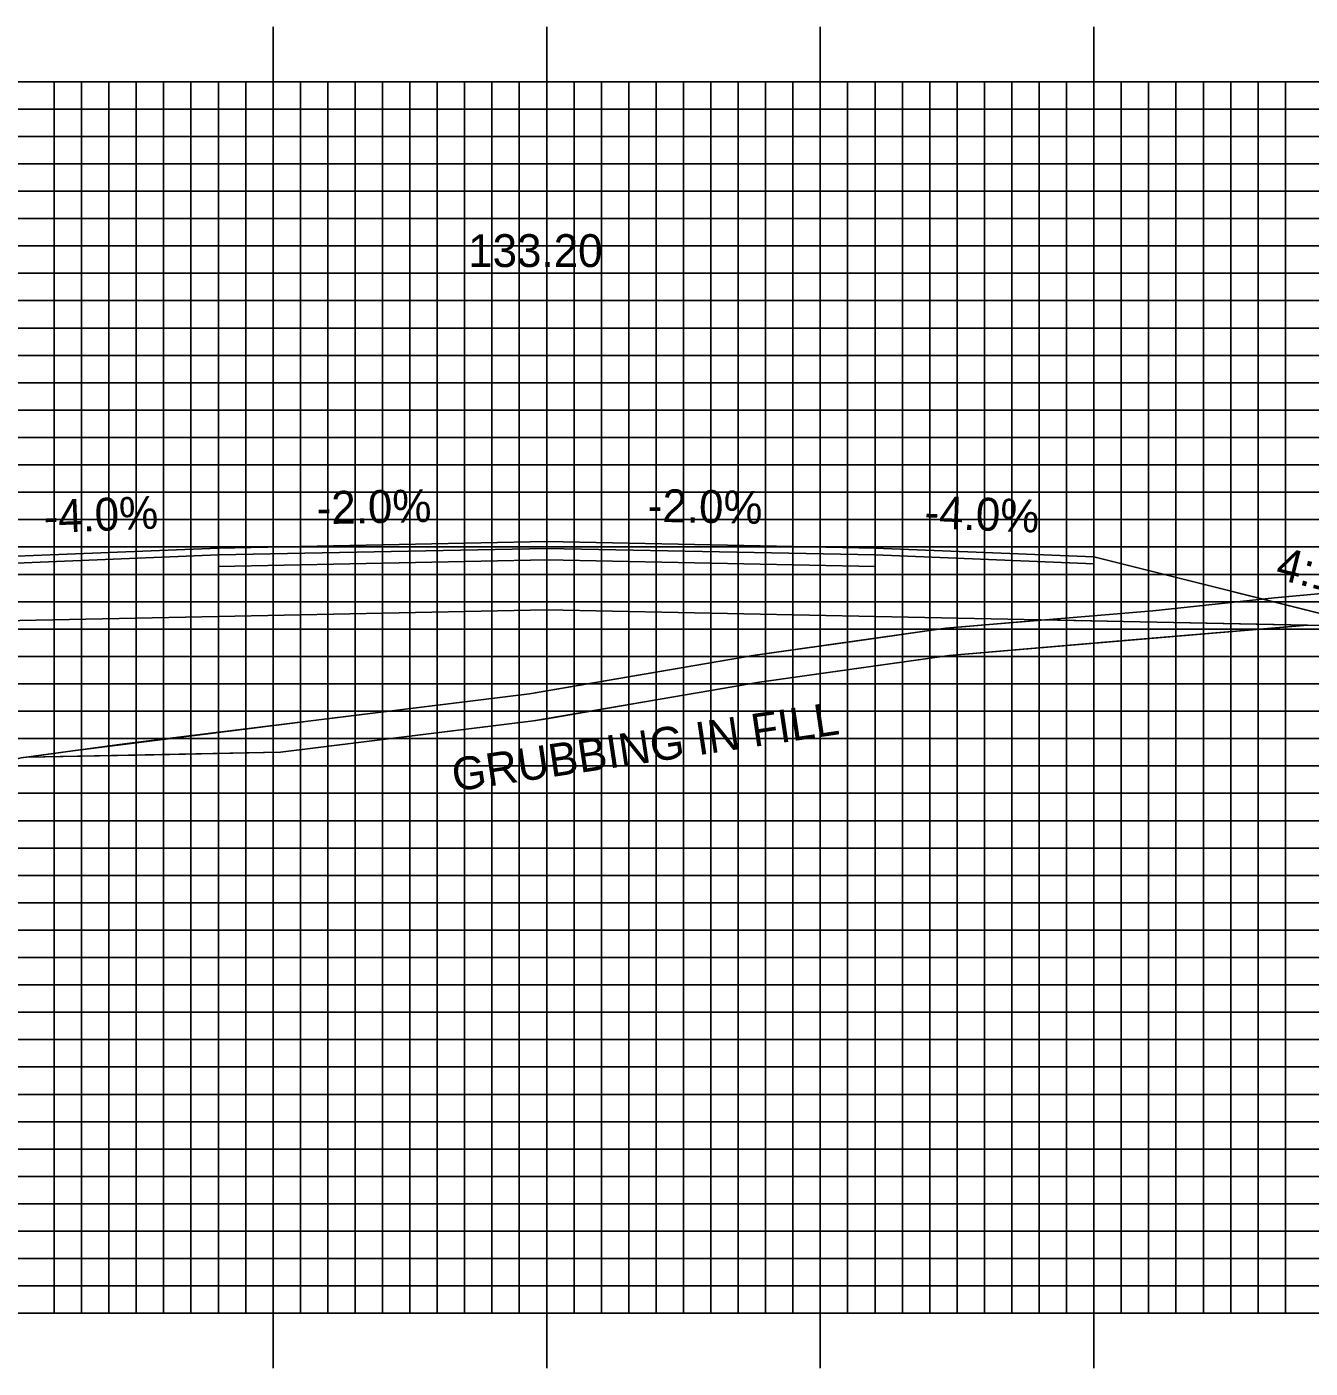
# Model space of a CAD drawing. Extents: x 1782254 to 1782597, y 442591 to 442811.
# Drawn here: x 1782400.43 to 1782447.34, y 442716.66 to 442765.67 of the extents above; entities that cross this region are included whole.
import ezdxf

# ---------------------------------------------------------------- set-up
doc = ezdxf.new("R2010")
doc.units = 0
for name, color, linetype in [('ANNOTATION', 7, 'Continuous'), ('D_Roadway_Centerline', 7, 'Continuous'), ('D_Roadway_Centerline_Text', 7, 'Continuous'), ('D_Roadway_Edge_Shoulder', 7, 'Continuous'), ('D_Roadway_Edge_TW', 7, 'Continuous'), ('D_Roadway_Pavement', 7, 'Continuous'), ('D_Roadway_SlopeLines', 7, 'Continuous'), ('D_Roadway_SubGrade', 7, 'Continuous'), ('GRUBBING IN FILL', 7, 'Continuous'), ('MAJOR', 7, 'Continuous'), ('MINOR', 7, 'Continuous'), ('S_Roadway_Centerline', 7, 'Continuous')]:
    doc.layers.add(name, color=color, linetype=linetype)

msp = doc.modelspace()

# ---------------------------------------------------------------- linework, layer by layer
at = {"layer": 'D_Roadway_Centerline'}
msp.add_lwpolyline([(1782351.984, 442731.486), (1782387.434, 442743.303), (1782389.26, 442743.759), (1782399.434, 442746.303), (1782407.434, 442746.623), (1782419.434, 442746.863), (1782431.434, 442746.623), (1782439.434, 442746.303), (1782449.608, 442743.759), (1782453.608, 442742.759), (1782457.483, 442744.696), (1782458.733, 442745.255), (1782459.983, 442745.682), (1782461.233, 442745.977), (1782462.483, 442746.14)], dxfattribs=at)
at = {"layer": 'D_Roadway_Edge_Shoulder'}
for points in [[(1782407.434, 442746.623), (1782399.434, 442746.303), (1782399.434, 442746.053), (1782407.434, 442746.373)], [(1782431.434, 442746.623), (1782439.434, 442746.303), (1782439.434, 442746.053), (1782431.434, 442746.373)]]:
    msp.add_lwpolyline(points, close=True, dxfattribs=at)
at = {"layer": 'D_Roadway_Edge_TW'}
msp.add_lwpolyline([(1782407.434, 442746.373), (1782407.434, 442746.623), (1782419.434, 442746.863), (1782431.434, 442746.623), (1782431.434, 442746.373), (1782419.434, 442746.613)], close=True, dxfattribs=at)
at = {"layer": 'D_Roadway_Pavement'}
msp.add_lwpolyline([(1782407.434, 442745.956), (1782407.434, 442746.373), (1782419.434, 442746.613), (1782431.434, 442746.373), (1782431.434, 442745.956), (1782419.434, 442746.196)], close=True, dxfattribs=at)
at = {"layer": 'D_Roadway_SlopeLines'}
msp.add_lwpolyline([(1782439.434, 442746.303), (1782453.608, 442742.759)], dxfattribs=at)
at = {"layer": 'D_Roadway_SubGrade'}
msp.add_lwpolyline([(1782407.434, 442744.123), (1782389.26, 442743.759), (1782399.434, 442746.303), (1782399.434, 442746.053), (1782407.434, 442746.373), (1782419.434, 442746.613), (1782431.434, 442746.373), (1782439.434, 442746.053), (1782439.434, 442746.303), (1782449.608, 442743.759), (1782431.434, 442744.123), (1782419.434, 442744.363)], close=True, dxfattribs=at)
at = {"layer": 'GRUBBING IN FILL'}
msp.add_line((1782400.434, 442738.983), (1782409.709, 442739.168), dxfattribs=at)
msp.add_line((1782400.434, 442738.983), (1782409.709, 442739.168), dxfattribs=at)
msp.add_lwpolyline([(1782409.709, 442739.168), (1782418.947, 442740.308), (1782427.208, 442741.722), (1782434.14, 442742.702), (1782447.244, 442743.806)], dxfattribs=at)
msp.add_lwpolyline([(1782409.709, 442739.168), (1782418.947, 442740.308), (1782427.208, 442741.722), (1782434.14, 442742.702), (1782447.244, 442743.806)], dxfattribs=at)
for points in [[(1782419.434, 442741.406), (1782422.928, 442742.004), (1782427.054, 442742.71), (1782430.541, 442743.203), (1782434.028, 442743.696), (1782437.621, 442743.999), (1782440.521, 442743.941), (1782447.244, 442743.806), (1782440.692, 442743.254), (1782434.14, 442742.702), (1782430.674, 442742.212), (1782427.208, 442741.722), (1782423.078, 442741.015), (1782419.434, 442740.391)], [(1782419.434, 442741.406), (1782422.928, 442742.004), (1782427.054, 442742.71), (1782430.541, 442743.203), (1782434.028, 442743.696), (1782437.621, 442743.999), (1782440.521, 442743.941), (1782447.244, 442743.806), (1782440.692, 442743.254), (1782434.14, 442742.702), (1782430.674, 442742.212), (1782427.208, 442741.722), (1782423.078, 442741.015), (1782419.434, 442740.391)], [(1782400.434, 442738.983), (1782402.117, 442739.213), (1782411.403, 442740.385), (1782418.802, 442741.297), (1782419.434, 442741.406), (1782419.434, 442740.391), (1782418.947, 442740.308), (1782414.328, 442739.738), (1782409.709, 442739.168), (1782405.071, 442739.075)], [(1782400.434, 442738.983), (1782402.117, 442739.213), (1782411.403, 442740.385), (1782418.802, 442741.297), (1782419.434, 442741.406), (1782419.434, 442740.391), (1782418.947, 442740.308), (1782414.328, 442739.738), (1782409.709, 442739.168), (1782405.071, 442739.075)]]:
    msp.add_lwpolyline(points, close=True, dxfattribs=at)
at = {"layer": 'MAJOR'}
for p, q in [((1782409.434, 442765.669), (1782409.434, 442763.665)), ((1782419.434, 442765.669), (1782419.434, 442763.665)), ((1782429.434, 442765.669), (1782429.434, 442763.665)), ((1782439.434, 442765.669), (1782439.434, 442763.665)), ((1782279.434, 442763.665), (1782559.434, 442763.665)), ((1782279.434, 442763.665), (1782559.434, 442763.665)), ((1782409.434, 442718.665), (1782409.434, 442763.665)), ((1782419.434, 442718.665), (1782419.434, 442763.665)), ((1782429.434, 442718.665), (1782429.434, 442763.665)), ((1782439.434, 442718.665), (1782439.434, 442763.665)), ((1782279.434, 442758.665), (1782559.434, 442758.665)), ((1782279.434, 442753.665), (1782559.434, 442753.665)), ((1782279.434, 442748.665), (1782559.434, 442748.665)), ((1782279.434, 442743.665), (1782559.434, 442743.665)), ((1782279.434, 442738.665), (1782559.434, 442738.665)), ((1782279.434, 442733.665), (1782559.434, 442733.665)), ((1782279.434, 442728.665), (1782559.434, 442728.665)), ((1782279.434, 442723.665), (1782559.434, 442723.665)), ((1782279.434, 442718.665), (1782559.434, 442718.665)), ((1782279.434, 442718.665), (1782559.434, 442718.665)), ((1782409.434, 442716.661), (1782409.434, 442718.665)), ((1782419.434, 442716.661), (1782419.434, 442718.665)), ((1782429.434, 442716.661), (1782429.434, 442718.665)), ((1782439.434, 442716.661), (1782439.434, 442718.665))]:
    msp.add_line(p, q, dxfattribs=at)
at = {"layer": 'MINOR'}
for p, q in [((1782401.434, 442718.665), (1782401.434, 442763.665)), ((1782402.434, 442718.665), (1782402.434, 442763.665)), ((1782403.434, 442718.665), (1782403.434, 442763.665)), ((1782404.434, 442718.665), (1782404.434, 442763.665)), ((1782405.434, 442718.665), (1782405.434, 442763.665)), ((1782406.434, 442718.665), (1782406.434, 442763.665)), ((1782407.434, 442718.665), (1782407.434, 442763.665)), ((1782408.434, 442718.665), (1782408.434, 442763.665)), ((1782410.434, 442718.665), (1782410.434, 442763.665)), ((1782411.434, 442718.665), (1782411.434, 442763.665)), ((1782412.434, 442718.665), (1782412.434, 442763.665)), ((1782413.434, 442718.665), (1782413.434, 442763.665)), ((1782414.434, 442718.665), (1782414.434, 442763.665)), ((1782415.434, 442718.665), (1782415.434, 442763.665)), ((1782416.434, 442718.665), (1782416.434, 442763.665)), ((1782417.434, 442718.665), (1782417.434, 442763.665)), ((1782418.434, 442718.665), (1782418.434, 442763.665)), ((1782420.434, 442718.665), (1782420.434, 442763.665)), ((1782421.434, 442718.665), (1782421.434, 442763.665)), ((1782422.434, 442718.665), (1782422.434, 442763.665)), ((1782423.434, 442718.665), (1782423.434, 442763.665)), ((1782424.434, 442718.665), (1782424.434, 442763.665)), ((1782425.434, 442718.665), (1782425.434, 442763.665)), ((1782426.434, 442718.665), (1782426.434, 442763.665)), ((1782427.434, 442718.665), (1782427.434, 442763.665)), ((1782428.434, 442718.665), (1782428.434, 442763.665)), ((1782430.434, 442718.665), (1782430.434, 442763.665)), ((1782431.434, 442718.665), (1782431.434, 442763.665)), ((1782432.434, 442718.665), (1782432.434, 442763.665)), ((1782433.434, 442718.665), (1782433.434, 442763.665)), ((1782434.434, 442718.665), (1782434.434, 442763.665)), ((1782435.434, 442718.665), (1782435.434, 442763.665)), ((1782436.434, 442718.665), (1782436.434, 442763.665)), ((1782437.434, 442718.665), (1782437.434, 442763.665)), ((1782438.434, 442718.665), (1782438.434, 442763.665)), ((1782440.434, 442718.665), (1782440.434, 442763.665)), ((1782441.434, 442718.665), (1782441.434, 442763.665)), ((1782442.434, 442718.665), (1782442.434, 442763.665)), ((1782443.434, 442718.665), (1782443.434, 442763.665)), ((1782444.434, 442718.665), (1782444.434, 442763.665)), ((1782445.434, 442718.665), (1782445.434, 442763.665)), ((1782446.434, 442718.665), (1782446.434, 442763.665)), ((1782279.434, 442762.665), (1782559.434, 442762.665)), ((1782279.434, 442761.665), (1782559.434, 442761.665)), ((1782279.434, 442760.665), (1782559.434, 442760.665)), ((1782279.434, 442759.665), (1782559.434, 442759.665)), ((1782279.434, 442757.665), (1782559.434, 442757.665)), ((1782279.434, 442756.665), (1782559.434, 442756.665)), ((1782279.434, 442755.665), (1782559.434, 442755.665)), ((1782279.434, 442754.665), (1782559.434, 442754.665)), ((1782279.434, 442752.665), (1782559.434, 442752.665)), ((1782279.434, 442751.665), (1782559.434, 442751.665)), ((1782279.434, 442750.665), (1782559.434, 442750.665)), ((1782279.434, 442749.665), (1782559.434, 442749.665)), ((1782279.434, 442747.665), (1782559.434, 442747.665)), ((1782279.434, 442746.665), (1782559.434, 442746.665)), ((1782279.434, 442745.665), (1782559.434, 442745.665)), ((1782279.434, 442744.665), (1782559.434, 442744.665)), ((1782279.434, 442742.665), (1782559.434, 442742.665)), ((1782279.434, 442741.665), (1782559.434, 442741.665)), ((1782279.434, 442740.665), (1782559.434, 442740.665)), ((1782279.434, 442739.665), (1782559.434, 442739.665)), ((1782279.434, 442737.665), (1782559.434, 442737.665)), ((1782279.434, 442736.665), (1782559.434, 442736.665)), ((1782279.434, 442735.665), (1782559.434, 442735.665)), ((1782279.434, 442734.665), (1782559.434, 442734.665)), ((1782279.434, 442732.665), (1782559.434, 442732.665)), ((1782279.434, 442731.665), (1782559.434, 442731.665)), ((1782279.434, 442730.665), (1782559.434, 442730.665)), ((1782279.434, 442729.665), (1782559.434, 442729.665)), ((1782279.434, 442727.665), (1782559.434, 442727.665)), ((1782279.434, 442726.665), (1782559.434, 442726.665)), ((1782279.434, 442725.665), (1782559.434, 442725.665)), ((1782279.434, 442724.665), (1782559.434, 442724.665)), ((1782279.434, 442722.665), (1782559.434, 442722.665)), ((1782279.434, 442721.665), (1782559.434, 442721.665)), ((1782279.434, 442720.665), (1782559.434, 442720.665)), ((1782279.434, 442719.665), (1782559.434, 442719.665))]:
    msp.add_line(p, q, dxfattribs=at)
at = {"layer": 'S_Roadway_Centerline'}
msp.add_lwpolyline([(1782346.891, 442731.172), (1782359.715, 442731.963), (1782365.175, 442733.019), (1782371.508, 442733.698), (1782381.434, 442734.81), (1782387.999, 442736.171), (1782395.979, 442737.945), (1782400.231, 442738.955), (1782404.003, 442739.472), (1782418.802, 442741.297), (1782427.054, 442742.71), (1782434.028, 442743.696), (1782441.593, 442744.334), (1782446.036, 442744.805), (1782450.006, 442745.176), (1782466.168, 442746.424), (1782469.44, 442746.736), (1782472.854, 442747.043)], dxfattribs=at)

# ---------------------------------------------------------------- texts
at = {"layer": 'ANNOTATION'}
for s, rotation, p in [('-2.0%', 1.1458, (1782411.04, 442747.495)), ('-2.0%', 358.8542, (1782423.12, 442747.589)), ('-4.0%', 2.2906, (1782401.066, 442747.17)), ('-4.0%', 357.7094, (1782433.226, 442747.353)), ('4:1', 345.9638, (1782446.027, 442745.516))]:
    msp.add_text(s, height=1.2, rotation=rotation, dxfattribs=at).set_placement(p)
at = {"layer": 'D_Roadway_Centerline'}
for s, p in [('C', (1782419.429, 442746.863)), ('L', (1782419.434, 442746.855))]:
    msp.add_text(s, height=0.0146, dxfattribs=at).set_placement(p)
at = {"layer": 'D_Roadway_Centerline_Text'}
msp.add_text('133.20', height=1.2, dxfattribs=at).set_placement((1782416.566, 442756.893))
at = {"layer": 'GRUBBING IN FILL'}
msp.add_text('GRUBBING IN FILL', height=1.2, rotation=8.4676, dxfattribs=at).set_placement((1782416.066, 442737.728))

doc.saveas('drawing.dxf')
